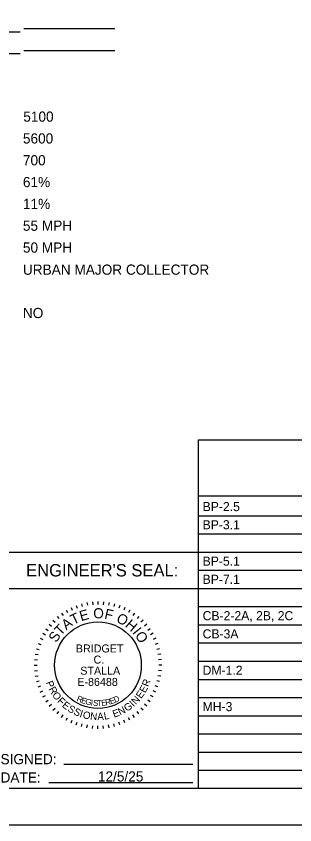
# Model space of a CAD drawing. Extents: x -107 to 120, y -81 to 213.
# Drawn here: x 11.53 to 15.36, y 1.57 to 12.69 of the extents above; entities that cross this region are included whole.
import ezdxf

# ---------------------------------------------------------------- set-up
doc = ezdxf.new("R2010")
doc.units = 0
for name, color, linetype in [('SH_Border', 7, 'Continuous'), ('SH_Cut_Line', 7, 'Continuous'), ('SH_Data', 7, 'Continuous'), ('SH_Text', 7, 'Continuous')]:
    doc.layers.add(name, color=color, linetype=linetype)

msp = doc.modelspace()

# ---------------------------------------------------------------- linework, layer by layer
at = {"layer": 'SH_Border'}
msp.add_lwpolyline([(5.389, 23.068), (37.389, 23.068), (37.389, 2.068), (5.389, 2.068)], close=True, dxfattribs=at)
at = {"layer": 'SH_Cut_Line'}
msp.add_lwpolyline([(3.889, 1.568), (37.889, 1.568), (37.889, 23.568), (3.889, 23.568)], close=True, dxfattribs=at)
at = {"layer": 'SH_Data'}
for p, q in [((11.589, 12.466), (8.634, 12.466)), ((12.889, 12.511), (11.639, 12.511)), ((11.589, 12.166), (7.236, 12.166)), ((12.889, 12.211), (11.639, 12.211)), ((14.039, 6.86), (27.489, 6.86)), ((14.039, 2.068), (14.039, 6.86)), ((14.039, 6.089), (27.489, 6.089)), ((14.039, 5.818), (27.489, 5.818)), ((14.039, 5.568), (27.489, 5.568)), ((14.039, 5.568), (27.489, 5.568)), ((11.239, 5.318), (14.039, 5.318)), ((14.039, 5.318), (27.489, 5.318)), ((14.039, 5.068), (27.489, 5.068)), ((11.239, 4.818), (14.039, 4.818)), ((14.039, 4.818), (27.489, 4.818)), ((12.358, 4.585), (12.371, 4.548)), ((12.431, 4.608), (12.441, 4.57)), ((12.505, 4.625), (12.512, 4.586)), ((12.581, 4.635), (12.584, 4.595)), ((12.657, 4.638), (12.657, 4.598)), ((12.733, 4.635), (12.73, 4.595)), ((12.809, 4.625), (12.802, 4.586)), ((12.883, 4.608), (12.873, 4.57)), ((12.956, 4.585), (12.943, 4.548)), ((14.039, 4.568), (27.489, 4.568)), ((12.155, 4.48), (12.178, 4.447)), ((12.22, 4.521), (12.24, 4.486)), ((12.287, 4.556), (12.304, 4.52)), ((13.027, 4.556), (13.01, 4.52)), ((13.095, 4.521), (13.075, 4.486)), ((13.159, 4.48), (13.136, 4.447)), ((12.038, 4.382), (12.067, 4.354)), ((12.095, 4.434), (12.12, 4.403)), ((13.219, 4.434), (13.194, 4.403)), ((13.276, 4.382), (13.247, 4.354)), ((11.94, 4.265), (11.973, 4.242)), ((11.987, 4.326), (12.017, 4.3)), ((13.327, 4.326), (13.297, 4.3)), ((13.374, 4.265), (13.341, 4.242)), ((14.039, 4.318), (27.489, 4.318)), ((11.864, 4.133), (11.9, 4.116)), ((11.899, 4.201), (11.934, 4.181)), ((13.415, 4.201), (13.38, 4.181)), ((13.45, 4.133), (13.414, 4.116)), ((11.835, 4.062), (11.872, 4.049)), ((13.479, 4.062), (13.442, 4.049)), ((14.039, 4.068), (27.489, 4.068)), ((11.795, 3.915), (11.835, 3.908)), ((11.812, 3.99), (11.85, 3.979)), ((13.502, 3.99), (13.464, 3.979)), ((13.519, 3.915), (13.479, 3.908)), ((11.785, 3.839), (11.825, 3.836)), ((13.529, 3.839), (13.489, 3.836)), ((14.039, 3.818), (27.489, 3.818)), ((11.782, 3.763), (11.822, 3.763)), ((11.785, 3.687), (11.825, 3.69)), ((13.529, 3.687), (13.489, 3.69)), ((13.532, 3.763), (13.492, 3.763)), ((11.795, 3.611), (11.835, 3.618)), ((13.519, 3.611), (13.479, 3.618)), ((14.039, 3.568), (27.489, 3.568)), ((11.812, 3.537), (11.85, 3.547)), ((11.835, 3.464), (11.872, 3.478)), ((13.479, 3.464), (13.442, 3.478)), ((13.502, 3.537), (13.464, 3.547)), ((11.864, 3.393), (11.9, 3.41)), ((11.899, 3.326), (11.934, 3.346)), ((13.415, 3.326), (13.38, 3.346)), ((13.45, 3.393), (13.414, 3.41)), ((11.94, 3.261), (11.973, 3.284)), ((11.987, 3.201), (12.017, 3.226)), ((13.327, 3.201), (13.297, 3.226)), ((13.374, 3.261), (13.341, 3.284)), ((14.039, 3.318), (27.489, 3.318)), ((12.038, 3.145), (12.067, 3.173)), ((12.095, 3.093), (12.12, 3.124)), ((13.219, 3.093), (13.194, 3.124)), ((13.276, 3.145), (13.247, 3.173)), ((12.155, 3.046), (12.178, 3.079)), ((12.22, 3.005), (12.24, 3.04)), ((12.287, 2.97), (12.304, 3.006)), ((13.027, 2.97), (13.01, 3.006)), ((13.095, 3.005), (13.075, 3.04)), ((13.159, 3.046), (13.136, 3.079)), ((14.039, 3.068), (27.489, 3.068)), ((12.358, 2.941), (12.371, 2.979)), ((12.431, 2.918), (12.441, 2.957)), ((12.505, 2.902), (12.512, 2.941)), ((12.581, 2.892), (12.584, 2.931)), ((12.657, 2.888), (12.657, 2.928)), ((12.733, 2.892), (12.73, 2.931)), ((12.809, 2.902), (12.802, 2.941)), ((12.883, 2.918), (12.873, 2.957)), ((12.956, 2.941), (12.943, 2.979)), ((14.039, 2.818), (27.489, 2.818)), ((14.039, 2.568), (27.489, 2.568)), ((14.039, 2.318), (27.489, 2.318))]:
    msp.add_line(p, q, dxfattribs=at)
msp.add_circle((12.657, 3.763), 0.595, dxfattribs=at)
at = {"layer": 'SH_Text'}
for p, q in [((12.19, 2.401), (13.96, 2.401)), ((11.982, 2.149), (13.96, 2.149))]:
    msp.add_line(p, q, dxfattribs=at)

# ---------------------------------------------------------------- texts
at = {"layer": 'SH_Data'}
for s, height, rotation, p in [('T', 0.14, 25.7167, (12.319, 4.315)), ('E', 0.14, 15.7571, (12.425, 4.367)), ('O', 0.14, 359.7812, (12.592, 4.407)), ('F', 0.14, 347.4362, (12.738, 4.405)), ('O', 0.14, 332.2586, (12.897, 4.365)), ('T', 0.14, 46.4344, (12.145, 4.16)), ('A', 0.14, 36.4747, (12.22, 4.241)), ('H', 0.14, 319.9136, (13.02, 4.299)), ('S', 0.14, 57.1924, (12.085, 4.065)), ('I', 0.14, 308.367, (13.123, 4.212)), ('O', 0.14, 303.1491, (13.159, 4.172)), ('R', 0.1, 69.2322, (13.349, 3.459)), ('P', 0.1, 291.494, (11.939, 3.525)), ('R', 0.1, 298.7311, (11.976, 3.435)), ('E', 0.1, 61.9951, (13.305, 3.373)), ('O', 0.1, 306.4666, (12.022, 3.352)), ('R', 0.0805, 336.8131, (12.357, 3.275)), ('D', 0.0805, 22.9274, (12.891, 3.245)), ('N', 0.1, 47.0224, (13.177, 3.214)), ('E', 0.1, 54.758, (13.25, 3.295)), ('F', 0.1, 314.7068, (12.091, 3.262)), ('E', 0.1, 321.4393, (12.155, 3.198)), ('E', 0.0805, 340.3929, (12.419, 3.248)), ('G', 0.0805, 347.5534, (12.478, 3.227)), ('I', 0.0805, 354.7035, (12.555, 3.209)), ('S', 0.0805, 354.7035, (12.586, 3.206)), ('T', 0.0805, 1.8292, (12.643, 3.201)), ('E', 0.0805, 5.3787, (12.705, 3.204)), ('R', 0.0805, 12.4427, (12.766, 3.21)), ('E', 0.0805, 19.4494, (12.832, 3.224)), ('G', 0.1, 35.0469, (13.055, 3.12)), ('I', 0.1, 43.287, (13.144, 3.185)), ('S', 0.1, 328.6764, (12.231, 3.138)), ('S', 0.1, 335.9134, (12.313, 3.09)), ('I', 0.1, 343.1505, (12.398, 3.053)), ('O', 0.1, 346.8859, (12.441, 3.038)), ('N', 0.1, 355.1261, (12.546, 3.015)), ('L', 0.1, 10.0987, (12.746, 3.012)), ('E', 0.1, 20.0742, (12.878, 3.04)), ('N', 0.1, 27.3113, (12.961, 3.071)), ('A', 0.1, 2.8617, (12.649, 3.007))]:
    msp.add_text(s, height=height, rotation=rotation, dxfattribs=at).set_placement(p)
for s, p in [('BRIDGET', (12.353, 3.938)), ('C.', (12.596, 3.785)), ('STALLA', (12.414, 3.632)), ('E-86488', (12.373, 3.478))]:
    msp.add_text(s, height=0.11, dxfattribs=at).set_placement(p)
at = {"layer": 'SH_Text'}
for s, height, p in [('5100', 0.14, (11.631, 11.235)), ('5600', 0.14, (11.626, 10.935)), ('700', 0.14, (11.626, 10.635)), ('61%', 0.14, (11.626, 10.335)), ('11%', 0.14, (11.626, 10.035)), ('55 MPH', 0.14, (11.626, 9.735)), ('50 MPH', 0.14, (11.626, 9.435)), ('URBAN MAJOR COLLECTOR', 0.14, (11.626, 9.131)), ('NO', 0.14, (11.626, 8.535)), ('BP-2.5', 0.125, (14.094, 5.881)), ('BP-3.1', 0.125, (14.094, 5.631)), ('BP-5.1', 0.125, (14.094, 5.131)), ("ENGINEER'S SEAL:", 0.17, (11.67, 4.983)), ('BP-7.1', 0.125, (14.094, 4.881)), ('CB-2-2A, 2B, 2C', 0.125, (14.094, 4.381)), ('CB-3A', 0.125, (14.094, 4.131)), ('DM-1.2', 0.125, (14.094, 3.631)), ('MH-3', 0.125, (14.094, 3.131)), ('SIGNED:', 0.14, (11.319, 2.401)), ('DATE:', 0.14, (11.319, 2.149)), ('12/5/25', 0.14, (12.656, 2.163))]:
    msp.add_text(s, height=height, dxfattribs=at).set_placement(p)

doc.saveas('drawing.dxf')
